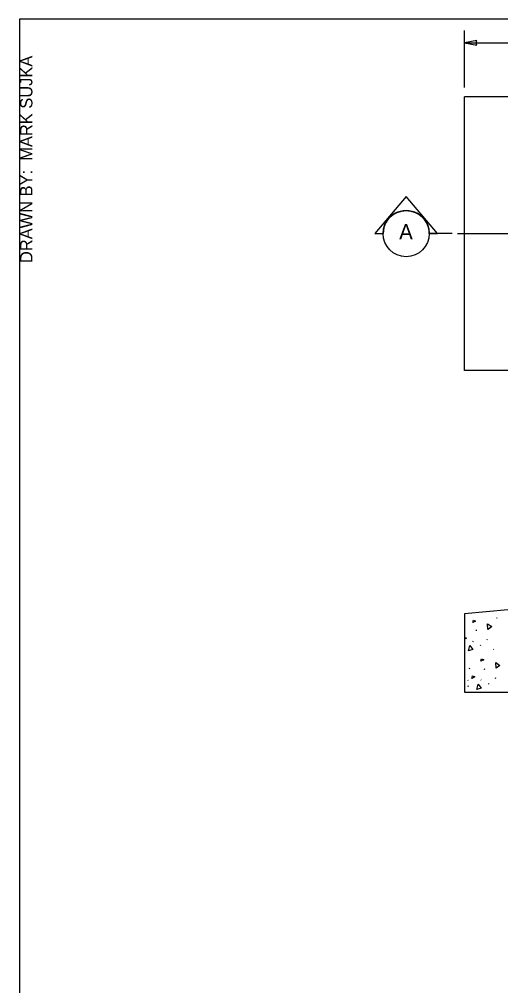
# Model space of a CAD drawing. Extents: x 99862 to 103151, y 100000 to 102076.
# Drawn here: x 99862 to 100488, y 100818 to 102076 of the extents above; entities that cross this region are included whole.
import ezdxf

# ---------------------------------------------------------------- set-up
doc = ezdxf.new("R2010")
doc.units = 0
for name, color, linetype in [('Level 1', 7, 'Continuous'), ('Level 11', 7, 'Continuous'), ('Level 15', 7, 'Continuous'), ('Level 16', 7, 'Continuous'), ('Level 17', 7, 'Continuous'), ('Level 20', 7, 'Continuous'), ('Level 62', 7, 'Continuous'), ('Level 9', 7, 'Continuous')]:
    doc.layers.add(name, color=color, linetype=linetype)

msp = doc.modelspace()

# ---------------------------------------------------------------- linework, layer by layer
at = {"layer": 'Level 1'}
msp.add_lwpolyline([(99862, 99999.5), (103151, 99999.5), (103151, 102075.5), (99862, 102075.5)], close=True, dxfattribs=at)
at = {"layer": 'Level 11'}
for p, q in [((100497.2, 101306.8), (100441.2, 101301.6)), ((100441.2, 101301.6), (100441.2, 101199.8)), ((100441.2, 101199.8), (100499.9, 101199.8))]:
    msp.add_line(p, q, dxfattribs=at)
at = {"layer": 'Level 15'}
for p, q in [((100441.2, 101986.8), (100441.2, 102060.8)), ((100441.2, 102044.8), (101459.2, 102044.8)), ((100432, 101796.6), (101468.7, 101796.6))]:
    msp.add_line(p, q, dxfattribs=at)
msp.add_lwpolyline([(100441.2, 102044.8), (100456.9, 102041.7), (100456.2, 102044.8), (100456.9, 102047.8)], close=True, dxfattribs=at)
at = {"layer": 'Level 16'}
for p, q in [((100482.8, 101297.1), (100483.2, 101296.1)), ((100456.5, 101279.6), (100456.8, 101280.8)), ((100470.6, 101267.8), (100470.9, 101269)), ((100451.6, 101266.3), (100452.2, 101265.7)), ((100461.9, 101260.4), (100462.1, 101261.6)), ((100478.7, 101255.9), (100479.4, 101255.2)), ((100447.7, 101230.3), (100447.9, 101231.5)), ((100467.2, 101229.3), (100467.5, 101230.5)), ((100481.3, 101217.5), (100481.6, 101218.7)), ((100445.3, 101215.6), (100445.9, 101214.9)), ((100446, 101207.4), (100446.3, 101208.6)), ((100462.3, 101216), (100462.9, 101215.3)), ((100472.6, 101210.1), (100472.8, 101211.3))]:
    msp.add_line(p, q, dxfattribs=at)
for points in [[(100451.7, 101290.3), (100452.6, 101293.7), (100455.4, 101292.4), (100451.7, 101290.3)], [(100471.6, 101281.5), (100471.1, 101288.6), (100476.4, 101285.1), (100471.7, 101281.5)], [(100441.2, 101271.1), (100443.6, 101270), (100441.2, 101268.6)], [(100446.2, 101253.6), (100448.1, 101260.5), (100451.9, 101255.4), (100446.3, 101253.7)], [(100462.4, 101240), (100463.2, 101243.4), (100466.1, 101242), (100462.4, 101240)], [(100482.3, 101231.2), (100481.8, 101238.3), (100487.1, 101234.7), (100482.4, 101231.2)], [(100450.6, 101217.6), (100451.5, 101221), (100454.3, 101219.7), (100450.6, 101217.6)], [(100456.9, 101203.3), (100458.8, 101210.2), (100462.6, 101205), (100457, 101203.3)]]:
    msp.add_lwpolyline(points, dxfattribs=at)
at = {"layer": 'Level 17'}
for p, q in [((100441.2, 101618.5), (100441.2, 101974.8)), ((101459.2, 101974.8), (100441.2, 101974.8)), ((101459.2, 101618.5), (100441.2, 101618.5))]:
    msp.add_line(p, q, dxfattribs=at)
at = {"layer": 'Level 9'}
for p, q in [((100365.2, 101845.1), (100324.6, 101796.6)), ((100405.8, 101796.6), (100365.2, 101845.1)), ((100324.6, 101796.6), (100335.2, 101796.6)), ((100395.2, 101796.6), (100405.8, 101796.6)), ((100425.2, 101796.6), (100395.2, 101796.6))]:
    msp.add_line(p, q, dxfattribs=at)
msp.add_circle((100365.2, 101796.6), 30, dxfattribs=at)
msp.add_arc((100365.2, 101796.6), 30, 359.9978, 180.0022, dxfattribs=at)

# ---------------------------------------------------------------- texts
at = {"layer": 'Level 20'}
msp.add_text('A', height=20, dxfattribs=at).set_placement((100356, 101789))
at = {"layer": 'Level 62'}
msp.add_text('DRAWN BY:  MARK SUJKA', height=16, rotation=90, dxfattribs=at).set_placement((99879, 101758.3))

doc.saveas('drawing.dxf')
